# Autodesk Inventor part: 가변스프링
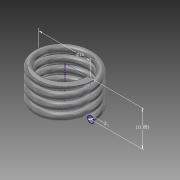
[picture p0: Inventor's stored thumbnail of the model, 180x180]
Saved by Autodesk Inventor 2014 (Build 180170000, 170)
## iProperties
Created: 2015-04
Part Number: 가변스프링
Material: 강철, 탄소
Document SubType Name: Modeling
Designer: basic
Mass: 4.97112 g
Surface Area: 12.741 cm^2
Volume: 0.631655 cm^3
Density: 7.87 g/cm^3
Appearance: 반연마
Author: basic
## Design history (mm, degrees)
sketch "스케치1"
  geometry: L1 (0, 0)-(-8, 0); L2 (-8, 0)-(-8, 11.05); L3 (-8, 11.05)-(0, 11.05); L4 (0, 11.05)-(0, 0); C1 r 1 at (-8, 0)
  constraints: 8 end point, 2 parallel, 1 centre point, 1 coincident, 1 horizontal, 1 perpendicular
  dimensions: "d0" = 2 diameter of C1; "d1" = 11.05025 distance between parallel lines of L1 L3 (derived); "d2" = 16 diameter of L2 L4
feature "코일1" sketch "스케치1" pitch "d3" = 10; turns "d5" = 4; dims "d4" = 11.05025 (= d1), "d6" = 0, angle "d7" = 90 deg, angle "d8" = 90 deg, "d9" = 0, "d10" = 0
sketch "스케치2"
  geometry: L1 (9, 0)-(7, 0) reference; 1 further point
  constraints: 1 horizontal alignment
extrude "돌출1" cut sketch "스케치2" distance "d11" = 10; taper "d12" = 0 deg
node "작업 평면1"
sketch "스케치3"
  geometry: L1 (1, 0)-(-1, 0) reference; 1 further point
  constraints: 1 horizontal alignment
extrude "돌출2" cut sketch "스케치3" distance "d14" = 10; taper "d15" = 0 deg
node "솔리드1"
node "절단 모서리 투영1"
node "절단 모서리 투영2"
other parameters: "d13" = 0
